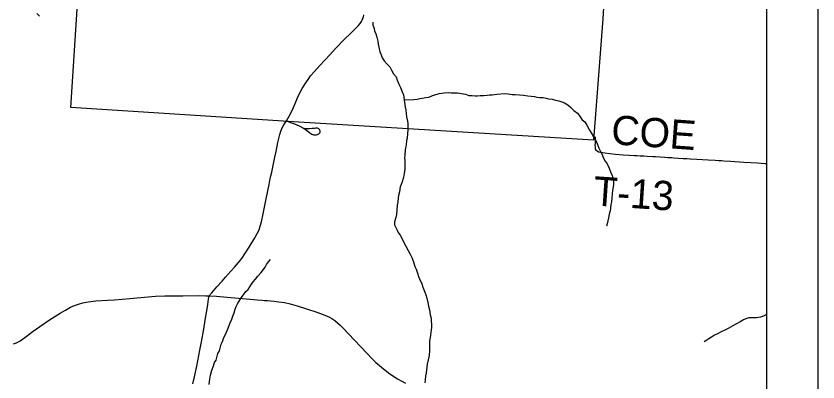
# Model space of a CAD drawing. Extents: x -8.2 to 34, y 0 to 22.
# Drawn here: x 7.441 to 9, y 18.032 to 18.744 of the extents above; entities that cross this region are included whole.
import ezdxf

# ---------------------------------------------------------------- set-up
doc = ezdxf.new("R2010")
doc.units = 0
for name, color, linetype in [('GM_X_Corporation', 7, 'Continuous'), ('GM_X_County_Road', 7, 'Continuous'), ('GM_X_Minor_River', 7, 'Continuous'), ('GM_X_Township_Road', 7, 'Continuous'), ('GM_X_Township_Road_Text', 7, 'Continuous'), ('SH_Data', 7, 'Continuous')]:
    doc.layers.add(name, color=color, linetype=linetype)

msp = doc.modelspace()

# ---------------------------------------------------------------- linework, layer by layer
at = {"layer": 'GM_X_Corporation'}
msp.add_lwpolyline([(7.6147, 19.5864), (8.6299, 19.5206), (8.6049, 19.1351), (8.5816, 18.7383), (8.5636, 18.5025), (7.9912, 18.537), (7.548, 18.5656), (7.5613, 18.7777), (7.5889, 19.1864)], close=True, dxfattribs=at)
at = {"layer": 'GM_X_County_Road'}
for points in [[(7.7852, 18.0289), (7.7883, 18.0422), (7.7928, 18.0629), (7.7988, 18.094), (7.8019, 18.1105), (7.8062, 18.135), (7.8091, 18.1521), (7.8117, 18.1674), (7.8123, 18.1704), (7.8142, 18.1827), (7.8155, 18.1931), (7.8162, 18.1968), (7.8173, 18.1997), (7.8188, 18.2024), (7.8217, 18.2056), (7.832, 18.2172), (7.8418, 18.2284), (7.8485, 18.2358), (7.8592, 18.2478), (7.8659, 18.2552), (7.874, 18.2646), (7.8801, 18.2725), (7.8863, 18.281), (7.8947, 18.2941), (7.9057, 18.3121), (7.9104, 18.3208), (7.9137, 18.3282), (7.9162, 18.3352), (7.9184, 18.3436), (7.9215, 18.3593), (7.9244, 18.3718), (7.9277, 18.3882), (7.9335, 18.4163), (7.935, 18.4236), (7.9369, 18.4327), (7.9384, 18.44), (7.9444, 18.4692), (7.9467, 18.4803), (7.9505, 18.4975), (7.9543, 18.5132), (7.9562, 18.5197), (7.9587, 18.5261), (7.9618, 18.5321), (7.967, 18.5399), (7.9722, 18.5488), (7.9761, 18.5561), (7.9806, 18.5657), (7.9887, 18.5847), (7.9937, 18.5953), (7.9978, 18.6029), (8.0046, 18.6138), (8.0102, 18.6222), (8.0139, 18.6272), (8.0208, 18.635), (8.0318, 18.6474), (8.051, 18.6683), (8.0625, 18.6807), (8.0801, 18.6983), (8.0917, 18.7095), (8.1021, 18.7199), (8.1065, 18.7247), (8.11, 18.7291), (8.1126, 18.7331), (8.1142, 18.7357), (8.1156, 18.7391), (8.1165, 18.7422), (8.1172, 18.7459)], [(7.4365, 18.1062), (7.4423, 18.1086), (7.4496, 18.1123), (7.4584, 18.1186), (7.4749, 18.131), (7.4877, 18.1402), (7.5064, 18.1532), (7.5274, 18.1661), (7.5375, 18.1718), (7.5476, 18.1773), (7.5553, 18.1809), (7.5629, 18.1836), (7.5712, 18.1858), (7.5815, 18.1877), (7.5963, 18.1897), (7.6195, 18.1915), (7.6328, 18.1921), (7.6625, 18.1942), (7.6767, 18.1956), (7.6983, 18.1979), (7.7125, 18.1991), (7.7305, 18.1997), (7.7479, 18.1999), (7.7659, 18.1998), (7.7969, 18.2), (7.8106, 18.1999), (7.8173, 18.1997)], [(7.8173, 18.1997), (7.8309, 18.1991), (7.8377, 18.1985), (7.8587, 18.1966), (7.8816, 18.1945), (7.9101, 18.1918), (7.92, 18.191), (7.9243, 18.1907), (7.9299, 18.1903), (7.936, 18.1899), (7.9434, 18.1892), (7.9519, 18.1881), (7.9629, 18.1864), (7.9743, 18.1839), (7.9881, 18.1802), (8.0058, 18.1746), (8.0258, 18.1679), (8.0415, 18.1622), (8.0505, 18.1584), (8.0553, 18.1557), (8.0609, 18.1519), (8.0663, 18.1474), (8.0715, 18.1425), (8.077, 18.1371), (8.0986, 18.1141), (8.1237, 18.0873), (8.1328, 18.078), (8.141, 18.0703), (8.1518, 18.061), (8.1655, 18.0502), (8.1756, 18.0428), (8.1829, 18.0381), (8.19, 18.0341), (8.1985, 18.0301)]]:
    msp.add_lwpolyline(points, dxfattribs=at)
at = {"layer": 'GM_X_Minor_River'}
for points in [[(7.4819, 18.7485), (7.4869, 18.7433)], [(8.1346, 18.7316), (8.135, 18.7266), (8.1372, 18.7194), (8.1383, 18.7148), (8.141, 18.7091), (8.1428, 18.7022), (8.1443, 18.6946), (8.145, 18.6889), (8.1465, 18.6828), (8.1484, 18.674), (8.151, 18.6679), (8.1529, 18.6626), (8.157, 18.6565), (8.1619, 18.6507), (8.1676, 18.645), (8.1714, 18.6385), (8.1751, 18.6313), (8.18, 18.6252), (8.1819, 18.6187), (8.1856, 18.6114), (8.1887, 18.6049), (8.192, 18.5962), (8.1943, 18.5905), (8.195, 18.5859), (8.1961, 18.5802), (8.1972, 18.5714), (8.1979, 18.5665), (8.1987, 18.5608), (8.1998, 18.5539), (8.2005, 18.5474), (8.202, 18.5394), (8.2027, 18.5345), (8.2031, 18.5288), (8.203, 18.5223), (8.2022, 18.5155), (8.2014, 18.5063), (8.2002, 18.5014), (8.1994, 18.4926), (8.1983, 18.4873), (8.1975, 18.4827), (8.197, 18.4732), (8.1966, 18.4679), (8.197, 18.4618), (8.1973, 18.4542), (8.1973, 18.4451), (8.1957, 18.4379), (8.1949, 18.4329), (8.1937, 18.4276), (8.1918, 18.4215), (8.1902, 18.4162), (8.1883, 18.4113), (8.1864, 18.4021), (8.1848, 18.3945), (8.1844, 18.39), (8.1836, 18.3816), (8.1824, 18.3759), (8.1816, 18.366), (8.1812, 18.358), (8.1796, 18.3519), (8.1773, 18.3436), (8.1772, 18.3375), (8.1821, 18.3276), (8.1844, 18.3226), (8.1882, 18.3176), (8.1923, 18.3093), (8.1957, 18.302), (8.1991, 18.2963), (8.2036, 18.2875), (8.2073, 18.2806), (8.2104, 18.2741), (8.2137, 18.2658), (8.2167, 18.257), (8.2193, 18.2513), (8.222, 18.2436), (8.2235, 18.2372), (8.2257, 18.2326), (8.2298, 18.2227), (8.2321, 18.2162), (8.2358, 18.207), (8.2377, 18.2013), (8.2399, 18.1948), (8.2418, 18.1865), (8.2433, 18.1796), (8.2448, 18.1724), (8.2466, 18.1625), (8.2481, 18.1564), (8.2484, 18.151), (8.2492, 18.1438), (8.2491, 18.1381), (8.2483, 18.1335), (8.2471, 18.1233), (8.2464, 18.1187), (8.2452, 18.1122), (8.2451, 18.0989), (8.2447, 18.0936), (8.2443, 18.0837), (8.2427, 18.075), (8.2407, 18.0666), (8.2399, 18.0609), (8.2384, 18.0499), (8.2372, 18.0442)], [(8.1961, 18.5805), (8.2144, 18.5812), (8.2209, 18.5823), (8.2262, 18.5834), (8.2307, 18.5838), (8.238, 18.5849), (8.2437, 18.586), (8.2494, 18.5883), (8.2555, 18.5905), (8.2639, 18.5931), (8.2692, 18.5939), (8.2738, 18.5942), (8.2814, 18.595), (8.2871, 18.5946), (8.2943, 18.5945), (8.2993, 18.5941), (8.3069, 18.5929), (8.3152, 18.5914), (8.3213, 18.5894), (8.3277, 18.589), (8.3335, 18.5886), (8.3384, 18.5886), (8.3433, 18.5889), (8.3506, 18.5893), (8.357, 18.5896), (8.3616, 18.5904), (8.3665, 18.5907), (8.3757, 18.5914), (8.3909, 18.5929), (8.3981, 18.5921), (8.4057, 18.5913), (8.4118, 18.5913), (8.4202, 18.5904), (8.4278, 18.5896), (8.4361, 18.5885), (8.449, 18.5873), (8.4536, 18.5861), (8.4597, 18.5853), (8.4658, 18.5849), (8.4715, 18.5837), (8.476, 18.5829), (8.4832, 18.5818), (8.4897, 18.5798), (8.4962, 18.579), (8.5022, 18.5767), (8.5075, 18.5748), (8.514, 18.5709), (8.5193, 18.5664), (8.5257, 18.5598), (8.5325, 18.5545), (8.5363, 18.5499), (8.542, 18.5415), (8.5469, 18.5377), (8.551, 18.5312), (8.5559, 18.5216), (8.5619, 18.5125), (8.5646, 18.5068), (8.568, 18.5018), (8.571, 18.4957), (8.574, 18.4865), (8.5774, 18.4804), (8.5804, 18.4743), (8.5826, 18.4686), (8.5864, 18.4617), (8.5901, 18.456), (8.5939, 18.4476), (8.5965, 18.4404), (8.5999, 18.4339), (8.6014, 18.4286), (8.6025, 18.4221), (8.6025, 18.416), (8.6009, 18.4038), (8.6001, 18.3989), (8.5993, 18.3898), (8.5989, 18.3825), (8.5977, 18.3772), (8.5965, 18.3704), (8.5961, 18.365), (8.5945, 18.3586), (8.593, 18.351), (8.5918, 18.3456), (8.5906, 18.3399), (8.5891, 18.3354)], [(7.8165, 18.0273), (7.8173, 18.033), (7.8181, 18.0379), (7.8193, 18.0452), (7.822, 18.055), (7.8243, 18.0615), (7.827, 18.0702), (7.8301, 18.0748), (7.8336, 18.0877), (7.8366, 18.093), (7.8401, 18.1056), (7.8428, 18.1112), (7.8452, 18.1185), (7.8482, 18.1234), (7.8521, 18.1333), (7.8575, 18.1469), (7.8606, 18.1545), (7.8625, 18.1599), (7.8652, 18.1663), (7.8671, 18.1735), (7.8695, 18.1792), (7.8721, 18.1838), (7.8748, 18.1891), (7.8787, 18.1959), (7.8837, 18.2016), (7.8883, 18.2084), (7.8928, 18.2122), (7.899, 18.2225), (7.9024, 18.227), (7.9066, 18.2323), (7.9112, 18.2376), (7.9178, 18.2452), (7.9223, 18.2509), (7.9254, 18.2554), (7.9281, 18.2607), (7.9323, 18.2657), (7.9358, 18.2702)], [(8.9, 18.1631), (8.8942, 18.1599), (8.8885, 18.1581), (8.8805, 18.157), (8.8752, 18.157), (8.8657, 18.1566), (8.86, 18.1552), (8.8554, 18.1533), (8.8485, 18.1491), (8.8416, 18.1454), (8.8344, 18.1416), (8.8252, 18.1363), (8.8203, 18.1333), (8.8119, 18.1295), (8.8046, 18.1258), (8.7989, 18.1231), (8.7932, 18.1193), (8.7882, 18.1159), (8.7837, 18.1133), (8.7791, 18.1103)], [(8.2372, 18.0442), (8.2368, 18.0354), (8.236, 18.0305)]]:
    msp.add_lwpolyline(points, dxfattribs=at)
at = {"layer": 'GM_X_Township_Road'}
for points in [[(7.967, 18.5399), (7.975, 18.5369), (7.9829, 18.5338), (7.9917, 18.53), (8, 18.5257), (8.0022, 18.5242), (8.0051, 18.5222), (8.0124, 18.5164), (8.0161, 18.5142), (8.0175, 18.5136), (8.019, 18.5131), (8.0203, 18.5128), (8.0214, 18.5126), (8.0235, 18.5125), (8.0255, 18.5127), (8.0274, 18.5132), (8.0288, 18.5138), (8.0299, 18.5144), (8.0308, 18.5151), (8.0312, 18.5157), (8.0318, 18.5167), (8.0322, 18.5177), (8.0323, 18.5186), (8.0323, 18.5199), (8.0322, 18.5206), (8.0317, 18.522), (8.031, 18.523), (8.03, 18.524), (8.0292, 18.5245), (8.0285, 18.5249), (8.0275, 18.5253), (8.0268, 18.5254), (8.0258, 18.5255), (8.0242, 18.5255), (8.0213, 18.5252), (8.0172, 18.5247), (8.0117, 18.5243), (8.0073, 18.5242), (8.005, 18.5244), (8.0019, 18.5248)], [(8.5673, 18.5086), (8.5667, 18.4961), (8.5665, 18.4924), (8.5667, 18.4884), (8.5673, 18.485), (8.5685, 18.4829), (8.5707, 18.4815), (8.5733, 18.4799), (8.5775, 18.4787), (8.5855, 18.4776), (8.5954, 18.4764), (8.6065, 18.4752), (8.6212, 18.4739), (8.6333, 18.4732), (8.6425, 18.4727), (8.6485, 18.4725), (8.6546, 18.4721), (8.6613, 18.4717), (8.668, 18.4712), (8.6791, 18.4706), (8.684, 18.4703), (8.7025, 18.4692), (8.708, 18.4689), (8.716, 18.4684), (8.7198, 18.4681), (8.7377, 18.4669), (8.7452, 18.4665), (8.7514, 18.4662), (8.7644, 18.4654), (8.7867, 18.464), (8.8003, 18.4632), (8.8065, 18.4629), (8.8114, 18.4626), (8.8126, 18.4625), (8.8169, 18.4623), (8.8303, 18.4613), (8.8562, 18.4597), (8.8823, 18.458), (8.8897, 18.4575), (8.8965, 18.457), (8.9, 18.4567)]]:
    msp.add_lwpolyline(points, dxfattribs=at)
at = {"layer": 'SH_Data'}
for p, q in [((9, 21), (9, 14)), ((8.9, 20.9), (8.9, 14.1))]:
    msp.add_line(p, q, dxfattribs=at)

# ---------------------------------------------------------------- texts
at = {"layer": 'GM_X_Township_Road_Text'}
for s, rotation, p in [('COE', 355.8896, (8.5968, 18.4947)), ('T-13', 356.1149, (8.5619, 18.3756))]:
    msp.add_text(s, height=0.05682, rotation=rotation, dxfattribs=at).set_placement(p)

doc.saveas('drawing.dxf')
